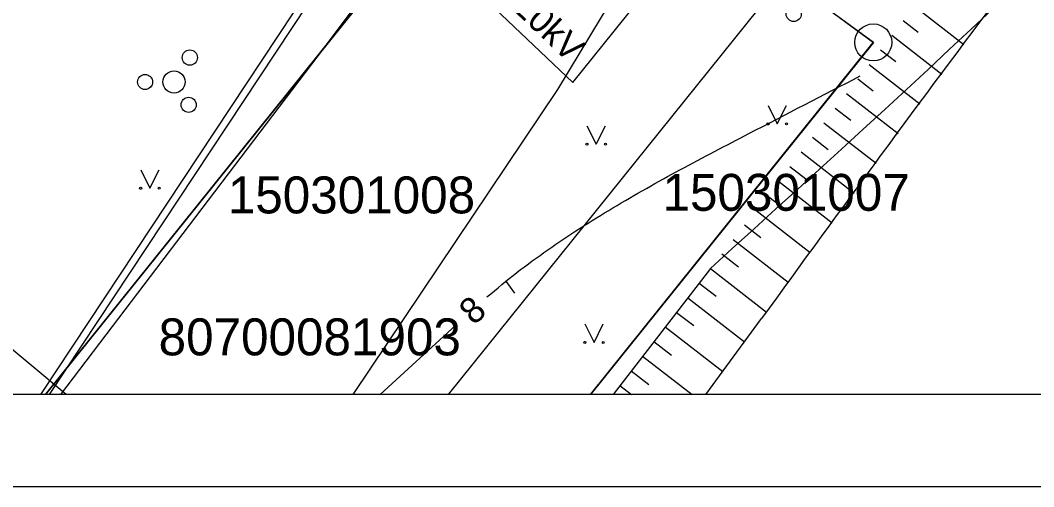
# Model space of a CAD drawing. Extents: x 514086 to 514457, y 297399 to 297567.
# Drawn here: x 514219.51 to 514246.93, y 297398.72 to 297411.35 of the extents above; entities that cross this region are included whole.
import ezdxf

# ---------------------------------------------------------------- set-up
doc = ezdxf.new("R2010")
doc.units = 0
for name, color, linetype in [('Level 1', 7, 'Continuous'), ('Level 18', 7, 'Continuous'), ('Level 23', 7, 'Continuous'), ('Level 29', 7, 'Continuous'), ('Level 31', 7, 'Continuous'), ('Level 32', 7, 'Continuous'), ('Level 36', 7, 'Continuous'), ('Level 37', 7, 'Continuous'), ('Level 46', 7, 'Continuous'), ('Level 59', 7, 'Continuous'), ('Level 61', 7, 'Continuous'), ('Level 63', 7, 'Continuous'), ('Level 7', 7, 'Continuous')]:
    doc.layers.add(name, color=color, linetype=linetype)

msp = doc.modelspace()

# ---------------------------------------------------------------- linework, layer by layer
at = {"layer": 'Level 1'}
for centre, radius in [((514240.437, 297411.519), 0.205), ((514224.095, 297410.338), 0.207), ((514222.884, 297409.678), 0.204), ((514223.668, 297409.678), 0.301), ((514224.063, 297409.058), 0.205)]:
    msp.add_circle(centre, radius, dxfattribs=at)
at = {"layer": 'Level 18'}
msp.add_line((514220.745, 297401.223), (514213.829, 297406.974), dxfattribs=at)
at = {"layer": 'Level 23'}
for p, q in [((514239.741, 297409.043), (514239.991, 297408.543)), ((514239.991, 297408.543), (514240.241, 297409.043)), ((514234.842, 297408.495), (514235.092, 297407.995)), ((514235.092, 297407.995), (514235.342, 297408.495)), ((514222.765, 297407.302), (514223.015, 297406.802)), ((514223.015, 297406.802), (514223.265, 297407.302)), ((514234.784, 297403.131), (514235.034, 297402.631)), ((514235.034, 297402.631), (514235.284, 297403.131))]:
    msp.add_line(p, q, dxfattribs=at)
for centre, radius in [((514239.741, 297408.542), 0.028), ((514240.241, 297408.542), 0.0263), ((514234.841, 297407.994), 0.028), ((514235.341, 297407.994), 0.0263), ((514222.764, 297406.801), 0.028), ((514223.264, 297406.801), 0.0263), ((514234.784, 297402.63), 0.028), ((514235.284, 297402.63), 0.0263)]:
    msp.add_circle(centre, radius, dxfattribs=at)
at = {"layer": 'Level 29'}
for p, q in [((514220.185, 297401.223), (514230.166, 297413.646)), ((514241.366, 297411.646), (514242.591, 297410.75)), ((514242.591, 297410.75), (514234.937, 297401.223))]:
    msp.add_line(p, q, dxfattribs=at)
at = {"layer": 'Level 31'}
for p, q in [((514243.708, 297411.733), (514245.041, 297410.697)), ((514243.401, 297411.339), (514243.804, 297411.025)), ((514243.094, 297410.944), (514244.447, 297409.892)), ((514242.787, 297410.55), (514243.196, 297410.231)), ((514242.48, 297410.155), (514243.853, 297409.087)), ((514242.173, 297409.76), (514242.588, 297409.437)), ((514241.866, 297409.366), (514243.259, 297408.282)), ((514241.559, 297408.971), (514241.98, 297408.644)), ((514241.252, 297408.576), (514242.666, 297407.477)), ((514240.945, 297408.182), (514241.372, 297407.85)), ((514240.638, 297407.787), (514242.072, 297406.672)), ((514240.331, 297407.392), (514240.764, 297407.056)), ((514240.024, 297406.998), (514241.478, 297405.867)), ((514239.717, 297406.603), (514240.156, 297406.262)), ((514239.41, 297406.209), (514240.884, 297405.062)), ((514239.103, 297405.814), (514239.548, 297405.468)), ((514238.796, 297405.419), (514240.29, 297404.257)), ((514238.489, 297405.025), (514238.94, 297404.674)), ((514238.182, 297404.63), (514235.547, 297401.223)), ((514238.182, 297404.63), (514239.696, 297403.452)), ((514238.182, 297404.63), (514238.19, 297404.624)), ((514237.876, 297404.234), (514238.334, 297403.88)), ((514237.57, 297403.839), (514239.109, 297402.649)), ((514237.264, 297403.443), (514237.73, 297403.084)), ((514236.959, 297403.048), (514238.52, 297401.84)), ((514236.653, 297402.652), (514237.125, 297402.287)), ((514236.347, 297402.257), (514237.684, 297401.223)), ((514236.041, 297401.861), (514236.52, 297401.491)), ((514235.735, 297401.466), (514236.049, 297401.223))]:
    msp.add_line(p, q, dxfattribs=at)
msp.add_spline([(514238.182, 297404.63), (514268.566, 297443.685), (514271.22, 297450.146), (514276.219, 297454.734), (514284.527, 297466.568), (514290.967, 297471.565), (514316.058, 297506.3)], degree=3, dxfattribs=at)
at = {"layer": 'Level 32'}
for p, q in [((514232.647, 297404.286), (514232.881, 297403.961)), ((514229.243, 297401.223), (514231.289, 297403.096))]:
    msp.add_line(p, q, dxfattribs=at)
msp.add_spline([(514232.136, 297403.861), (514232.944, 297404.519), (514233.784, 297405.136), (514235.543, 297406.271), (514237.37, 297407.305), (514238.296, 297407.798), (514239.223, 297408.281), (514242.239, 297409.845)], degree=3, dxfattribs=at)
at = {"layer": 'Level 36'}
msp.add_line((514238.06, 297401.223), (514239.566, 297403.275), dxfattribs=at)
msp.add_spline([(514320.804, 297502.52), (514306.724, 297488.103), (514301.133, 297479.973), (514270.315, 297441.123), (514246.087, 297412.115), (514239.566, 297403.275)], degree=3, dxfattribs=at)
at = {"layer": 'Level 37'}
for points in [[(514237.507, 297427.371), (514237.405, 297423.511), (514227.557, 297410.382), (514220.597, 297401.223)], [(514228.516, 297401.223), (514234.052, 297409.474), (514243.929, 297425.848)]]:
    msp.add_lwpolyline(points, dxfattribs=at)
at = {"layer": 'Level 46'}
for p, q in [((514230.16, 297413.64), (514220.185, 297401.223)), ((514234.936, 297401.223), (514242.59, 297410.75))]:
    msp.add_line(p, q, dxfattribs=at)
for points in [[(514229.261, 297420.493), (514230.166, 297413.646), (514220.185, 297401.223)], [(514234.937, 297401.223), (514242.591, 297410.75), (514240.166, 297412.522), (514231.088, 297401.223)]]:
    msp.add_lwpolyline(points, dxfattribs=at)
msp.add_circle((514242.59, 297410.75), 0.5, dxfattribs=at)
at = {"layer": 'Level 61'}
msp.add_lwpolyline([(514228.605, 297413.892), (514229.168, 297414.699), (514234.462, 297409.66), (514239.192, 297415.557), (514243.591, 297423.09), (514250.856, 297428.146), (514250.871, 297429.329), (514257.62, 297437.772), (514268.028, 297450.791), (514271.687, 297455.368), (514283.043, 297472.127), (514296.63, 297489.788), (514299.744, 297491.72), (514308.223, 297503.049), (514310.505, 297506.097), (514314.057, 297510.598), (514322.921, 297521.831), (514325.028, 297524.077), (514326.601, 297524.074), (514327.377, 297523.947), (514343.661, 297512.323), (514343.876, 297512.066)], dxfattribs=at)
at = {"layer": 'Level 63'}
for p, q in [((514454.695, 297401.223), (514096.037, 297401.223)), ((514457.195, 297398.723), (514086.037, 297398.723))]:
    msp.add_line(p, q, dxfattribs=at)
at = {"layer": 'Level 7'}
for points in [[(514227.337, 297412.224), (514220.053, 297401.223)], [(514227.337, 297412.224), (514227.292, 297411.794), (514220.292, 297401.223)]]:
    msp.add_lwpolyline(points, dxfattribs=at)

# ---------------------------------------------------------------- texts
at = {"layer": 'Level 32'}
msp.add_text('8', height=0.7, rotation=42.4784, dxfattribs=at).set_placement((514231.783, 297403.074))
at = {"layer": 'Level 46'}
for s, p in [('150301008', (514225.122, 297406.121)), ('150301007', (514236.885, 297406.191))]:
    msp.add_text(s, height=1, dxfattribs=at).set_placement(p)
at = {"layer": 'Level 59'}
msp.add_text('80700081903', height=1, dxfattribs=at).set_placement((514223.25, 297402.279))
at = {"layer": 'Level 61'}
msp.add_text('el.kab.20kV', height=0.7, rotation=316.4147, dxfattribs=at).set_placement((514230.807, 297413.553))

doc.saveas('drawing.dxf')
